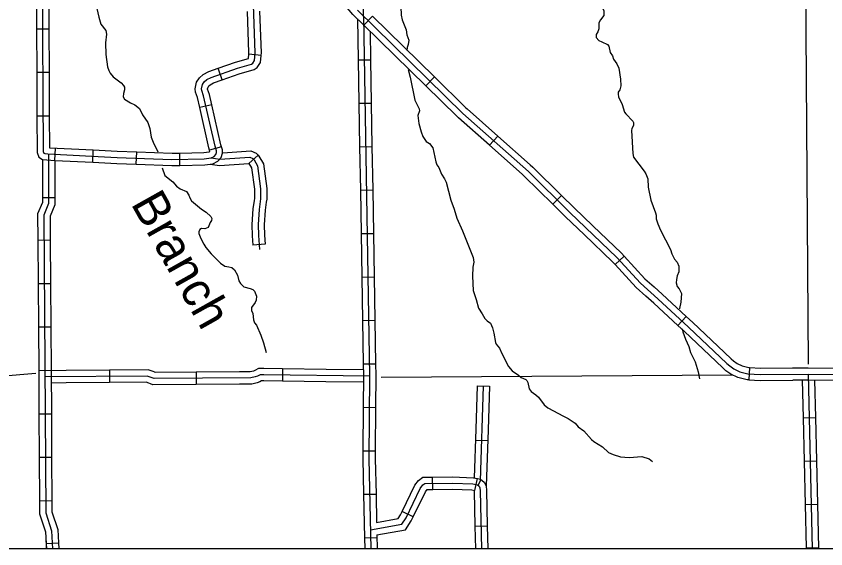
# Model space of a CAD drawing. Extents: x 1212896 to 1368412, y 378476 to 478763.
# Drawn here: x 1279495 to 1289328, y 388319 to 394792 of the extents above; entities that cross this region are included whole.
import ezdxf

# ---------------------------------------------------------------- set-up
doc = ezdxf.new("R2010")
doc.units = 0
for name, color, linetype in [('1', 7, 'Continuous'), ('Level 31', 7, 'Continuous'), ('Level 32', 7, 'Continuous'), ('Level 35', 7, 'Continuous'), ('Level 4', 7, 'Continuous'), ('Level 45', 7, 'Continuous'), ('Level 5', 7, 'Continuous')]:
    doc.layers.add(name, color=color, linetype=linetype)

msp = doc.modelspace()

# ---------------------------------------------------------------- linework, layer by layer
at = {"layer": '1'}
msp.add_lwpolyline([(1257400.3, 437504), (1319317.3, 437504), (1319317.3, 388319.3), (1257400.3, 388319.3)], close=True, dxfattribs=at)
at = {"layer": 'Level 31'}
for p, q in [((1283820.7, 394792.1), (1283715.7, 394684.9)), ((1284470, 393945.9), (1284575, 394053)), ((1285343.5, 393334.8), (1285244, 393222.6)), ((1285244, 393222.6), (1285244, 393222.6)), ((1285244, 393222.6), (1285244, 393222.6)), ((1286013.4, 392505.6), (1286118.8, 392612.4)), ((1286013.4, 392505.6), (1286013.4, 392505.6)), ((1286880, 391875.1), (1286769.4, 391773.8)), ((1287530.4, 391034.4), (1287632.3, 391144.5)), ((1287632.3, 391144.5), (1287632.3, 391144.5)), ((1287530.4, 391034.4), (1287530.4, 391034.4)), ((1288400.4, 390521.3), (1288393.8, 390371.5)), ((1288393.8, 390371.5), (1288393.8, 390371.5))]:
    msp.add_line(p, q, dxfattribs=at)
for points in [[(1283715.7, 394684.9), (1283584.6, 394813.4), (1283358, 395082)], [(1283638.6, 394863.5), (1284918.5, 393609.4), (1285715.4, 392903.1), (1286218.3, 392406.9), (1286791.1, 391859.1), (1287077.4, 391546.6), (1287288.1, 391358.8), (1287661.9, 391013.1), (1288126.6, 390571.2), (1288160.2, 390541.9), (1288211.1, 390506.9), (1288284.5, 390471.4), (1288382.2, 390445.7), (1288533.2, 390439), (1289114, 390442.4), (1294519.9, 390389.6)], [(1283820.7, 394792.1), (1284197.8, 394422.5)], [(1283715.7, 394684.9), (1284092.9, 394315.4)], [(1284197.8, 394422.5), (1284575, 394053)], [(1284470, 393945.9), (1284092.9, 394315.4)], [(1284575, 394053), (1284952.1, 393683.5)], [(1284847.1, 393576.3), (1284470, 393945.9)], [(1284952.1, 393683.5), (1284970.6, 393665.3), (1285343.5, 393334.8)], [(1285244, 393222.6), (1284868.3, 393555.6), (1284847.1, 393576.3)], [(1285343.5, 393334.8), (1285738.6, 392984.6)], [(1285244, 393222.6), (1285639.1, 392872.4)], [(1285738.6, 392984.6), (1285767.6, 392959), (1286118.8, 392612.4)], [(1286013.4, 392505.6), (1285665.1, 392849.4), (1285639.1, 392872.4)], [(1286118.8, 392612.4), (1286271.5, 392461.7), (1286497.2, 392245.9)], [(1286393.5, 392137.5), (1286167, 392354.1), (1286013.4, 392505.6)], [(1286497.2, 392245.9), (1286845.7, 391912.6), (1286880, 391875.1)], [(1286769.4, 391773.8), (1286738.5, 391807.6), (1286393.5, 392137.5)], [(1286880, 391875.1), (1287131.1, 391601.1), (1287242, 391502.2)], [(1286769.4, 391773.8), (1287025.6, 391494.2), (1287142.2, 391390.2)], [(1287242, 391502.2), (1287339.4, 391415.3), (1287632.3, 391144.5)], [(1287530.4, 391034.4), (1287238.6, 391304.3), (1287142.2, 391390.2)], [(1287632.3, 391144.5), (1287714.1, 391068.8), (1288016.7, 390781.1)], [(1287913.4, 390672.4), (1287611.5, 390959.4), (1287530.4, 391034.4)], [(1288016.7, 390781.1), (1288178.1, 390627.7), (1288207.1, 390602.3), (1288249.5, 390573.2), (1288311.1, 390543.4), (1288393.7, 390521.6), (1288400.4, 390521.3)], [(1288393.8, 390371.5), (1288371, 390372.5), (1288258.8, 390402), (1288174, 390443.1), (1288115, 390483.6), (1288077, 390516.8), (1287913.4, 390672.4)], [(1288400.4, 390521.3), (1288534.6, 390515.4), (1288924.4, 390517.7)], [(1288924.4, 390517.7), (1289114.1, 390518.8), (1289453.6, 390515.5)], [(1288393.8, 390371.5), (1288531.8, 390365.3), (1288925.3, 390367.7)], [(1289452.2, 390365.5), (1289113.9, 390368.8), (1288925.3, 390367.7)]]:
    msp.add_lwpolyline(points, dxfattribs=at)
at = {"layer": 'Level 32'}
for p, q in [((1279739.9, 394637.8), (1279889.9, 394638.8)), ((1282469.3, 394316), (1282320.1, 394331.7)), ((1283648.5, 394261.1), (1283798.4, 394263.6)), ((1279743.5, 394109.8), (1279893.4, 394110.9)), ((1281997.1, 394017.7), (1281947.5, 394159.3)), ((1281869.7, 393715.5), (1281723.4, 393682)), ((1283657.1, 393733.2), (1283807.1, 393735.6)), ((1279747, 393581.9), (1279897, 393582.9)), ((1279965.9, 393040), (1279973.4, 393189.8)), ((1280424, 393016.6), (1280431.5, 393166.4)), ((1280952.4, 392993.4), (1280958, 393143.3)), ((1281484.1, 392979.2), (1281481.6, 393129.1)), ((1281987.9, 393205.7), (1281844, 393163.2)), ((1283665.7, 393205.2), (1283815.7, 393207.7)), ((1279817.9, 393050.8), (1279963.6, 393039.6)), ((1283674.4, 392677.3), (1283824.4, 392679.8)), ((1279812.8, 392589.3), (1279962.8, 392588.6)), ((1283683, 392149.4), (1283833, 392151.8)), ((1279757.3, 392071.9), (1279907.3, 392072.9)), ((1283691.7, 391621.5), (1283841.7, 391623.9)), ((1279760.9, 391543.9), (1279910.9, 391544.9)), ((1283700.3, 391093.5), (1283850.3, 391096)), ((1279764.4, 391015.9), (1279914.4, 391016.9)), ((1283709, 390565.6), (1283858.9, 390568.1)), ((1279768, 390487.9), (1279918, 390488.9)), ((1283709.1, 390039.3), (1283859.1, 390038.4)), ((1279771.5, 389959.9), (1279921.5, 389960.9)), ((1289052.2, 389912.9), (1289202.1, 389916.2)), ((1283706.1, 389511.3), (1283856.1, 389510.4)), ((1279775.1, 389431.9), (1279925.1, 389432.9)), ((1289064, 389385), (1289213.9, 389388.4)), ((1284554.2, 389041.1), (1284552.7, 389191.1)), ((1285065.9, 389027), (1285095.6, 389174)), ((1279778.6, 388903.9), (1279928.6, 388904.9)), ((1283714.7, 388981.4), (1283864.7, 388984.6)), ((1289075.7, 388857.2), (1289225.7, 388860.5)), ((1284316.1, 388707), (1284180.9, 388772.1)), ((1285065.3, 388594.7), (1285215.3, 388598.3)), ((1283726, 388453.5), (1283876, 388456.7)), ((1279858.5, 388384.9), (1280008.4, 388391.6)), ((1289087.5, 388329.3), (1289237.5, 388332.6))]:
    msp.add_line(p, q, dxfattribs=at)
for points in [[(1279809.4, 395251.7), (1279823.5, 393145.8), (1279829.4, 393128.3), (1279840.9, 393121.6), (1279878.9, 393117.4), (1280719, 393075.7), (1281386.2, 393051.1), (1281779.2, 393057.7), (1281860.8, 393069.5), (1281898.3, 393088.4), (1281919.7, 393111.9), (1281927.2, 393135.1), (1281925.8, 393156.2), (1281909.6, 393210.9), (1281769.6, 393822.7), (1281748.2, 393889), (1281744.6, 393909.4), (1281755.5, 393960.5), (1281777.4, 393993.4), (1281808, 394020.6), (1281863.3, 394048.9), (1282181.9, 394160.5), (1282353.4, 394209.8), (1282368.4, 394220.3), (1282388.7, 394252.8), (1282398.6, 394347.3), (1282330.7, 396220.3)], [(1279736.4, 395165.8), (1279739.9, 394637.8)], [(1279886.4, 395166.8), (1279889.9, 394638.8)], [(1282320.1, 394331.7), (1282322.1, 394349.9), (1282304, 394848.5)], [(1282469.3, 394316), (1282472.3, 394344.7), (1282453.9, 394853.9)], [(1283713.4, 394790.2), (1283784.9, 390427.2), (1283779.1, 389413.7), (1283802.5, 388319.3)], [(1283640.3, 394758.8), (1283648.5, 394261.1)], [(1279739.9, 394637.8), (1279743.5, 394109.8)], [(1279889.9, 394638.8), (1279893.4, 394110.9)], [(1283792.8, 394609.4), (1283798.4, 394263.6)], [(1281947.5, 394159.3), (1282158.7, 394233.3), (1282314.4, 394278.1), (1282314.5, 394278.3), (1282320.1, 394331.7)], [(1281997.1, 394017.7), (1282204.3, 394090.3), (1282385.5, 394142.4), (1282423, 394168.6), (1282460.1, 394228.3), (1282469.3, 394316)], [(1283648.5, 394261.1), (1283657.1, 393733.2)], [(1283798.4, 394263.6), (1283807.1, 393735.6)], [(1279743.5, 394109.8), (1279747, 393581.9)], [(1279893.4, 394110.9), (1279897, 393582.9)], [(1281723.4, 393682), (1281695.9, 393802.4), (1281673.9, 393870.4), (1281666.7, 393910.7), (1281683.9, 393990.8), (1281719.3, 394043.9), (1281764.5, 394084.2), (1281833.1, 394119.3), (1281947.5, 394159.3)], [(1281869.7, 393715.5), (1281840.7, 393842.2), (1281819.8, 393906.9), (1281819.6, 393908.1), (1281824.6, 393931.4), (1281833.5, 393944.7), (1281849.9, 393959.4), (1281892.3, 393981.1), (1281997.1, 394017.7)], [(1281987.9, 393205.7), (1281980.8, 393229.6), (1281869.7, 393715.5)], [(1283657.1, 393733.2), (1283665.7, 393205.2)], [(1283807.1, 393735.6), (1283815.7, 393207.7)], [(1281844, 393163.2), (1281835.7, 393191.6), (1281723.4, 393682)], [(1279747, 393581.9), (1279750, 393133.6), (1279768.3, 393078.7), (1279814.8, 393051.6)], [(1279897, 393582.9), (1279899.6, 393192.9), (1279904.1, 393192.7)], [(1279904.1, 393192.7), (1280431.5, 393166.4)], [(1280431.5, 393166.4), (1280722.3, 393152), (1280958, 393143.3)], [(1280958, 393143.3), (1281387, 393127.6), (1281481.6, 393129.1)], [(1281481.6, 393129.1), (1281773.1, 393134), (1281837.6, 393143.3), (1281848.3, 393148.7), (1281844, 393163.2)], [(1281484.1, 392979.2), (1281785.1, 392984.2), (1281883.2, 392998.4), (1281943.5, 393028.7), (1281984.9, 393074.1), (1282001.6, 393126.1), (1281998.6, 393169.3), (1281987.9, 393205.7)], [(1283665.7, 393205.2), (1283674.4, 392677.3)], [(1283815.7, 393207.7), (1283824.4, 392679.8)], [(1279814.8, 393051.6), (1279812.8, 392589.3)], [(1279888.7, 393117), (1279886.1, 392514.2), (1279828.9, 392375.9), (1279853.2, 388757.5), (1279925.3, 388539.4), (1279935.2, 388319.3)], [(1279964.8, 393039.5), (1279962.8, 392588.6)], [(1279964.8, 393039.5), (1280424, 393016.6)], [(1280424, 393016.6), (1280715.9, 393002.1), (1280952.4, 392993.4)], [(1280952.4, 392993.4), (1281385.5, 392977.5), (1281484.1, 392979.2)], [(1283674.4, 392677.3), (1283683, 392149.4)], [(1283824.4, 392679.8), (1283833, 392151.8)], [(1279812.8, 392589.3), (1279812.6, 392529), (1279755.2, 392390.3), (1279757.3, 392071.9)], [(1279962.8, 392588.6), (1279962.4, 392498.8), (1279905.4, 392360.9), (1279907.3, 392072.9)], [(1283683, 392149.4), (1283691.7, 391621.5)], [(1283833, 392151.8), (1283841.7, 391623.9)], [(1279757.3, 392071.9), (1279760.9, 391543.9)], [(1279907.3, 392072.9), (1279910.9, 391544.9)], [(1283691.7, 391621.5), (1283700.3, 391093.5)], [(1283841.7, 391623.9), (1283850.3, 391096)], [(1279760.9, 391543.9), (1279764.4, 391015.9)], [(1279910.9, 391544.9), (1279914.4, 391016.9)], [(1283700.3, 391093.5), (1283709, 390565.6)], [(1283850.3, 391096), (1283858.9, 390568.1)], [(1279764.4, 391015.9), (1279768, 390487.9)], [(1279914.4, 391016.9), (1279918, 390488.9)], [(1283709, 390565.6), (1283711.2, 390426.8), (1283709.1, 390039.3)], [(1283858.9, 390568.1), (1283861.2, 390427.6), (1283859.1, 390038.4)], [(1279768, 390487.9), (1279771.5, 389959.9)], [(1279918, 390488.9), (1279921.5, 389960.9)], [(1289042, 390368.4), (1289052.2, 389912.9)], [(1289114, 390442.4), (1289161.4, 388319.3)], [(1289192.1, 390368), (1289202.1, 389916.2)], [(1283709.1, 390039.3), (1283706.1, 389511.3)], [(1283859.1, 390038.4), (1283856.1, 389510.4)], [(1279771.5, 389959.9), (1279775.1, 389431.9)], [(1279921.5, 389960.9), (1279925.1, 389432.9)], [(1289052.2, 389912.9), (1289064, 389385)], [(1289202.1, 389916.2), (1289213.9, 389388.4)], [(1283706.1, 389511.3), (1283705.5, 389413.1), (1283714.7, 388981.4)], [(1283856.1, 389510.4), (1283855.5, 389414.3), (1283864.7, 388984.6)], [(1279775.1, 389431.9), (1279778.6, 388903.9)], [(1279925.1, 389432.9), (1279928.6, 388904.9)], [(1289064, 389385), (1289075.7, 388857.2)], [(1289213.9, 389388.4), (1289225.7, 388860.5)], [(1284180.9, 388772.1), (1284335.4, 389092.7), (1284379.5, 389150), (1284432.3, 389189.9), (1284552.7, 389191.1)], [(1284552.7, 389191.1), (1284794.7, 389193.5), (1285048.4, 389183.5), (1285095.6, 389174)], [(1283798.1, 388549.4), (1284179.8, 388617.6), (1284229, 388695.8), (1284400.8, 389052.4), (1284433.8, 389095.2), (1284458.3, 389113.8), (1284793.5, 389117.1), (1285039.2, 389107.5), (1285097.4, 389095.7), (1285116.7, 389079.1), (1285126.1, 389062.3), (1285128.7, 389023.4), (1285145.5, 388319.3)], [(1285095.6, 389174), (1285132.1, 389166.6), (1285176.9, 389128.1), (1285201.1, 389084.5), (1285205.1, 389026.9), (1285215.3, 388598.3)], [(1284316.1, 388707), (1284463.8, 389013.6), (1284484.5, 389040.5), (1284554.2, 389041.1)], [(1284554.2, 389041.1), (1284792.5, 389043.5), (1285030.4, 389034.1), (1285065.9, 389027)], [(1285054.5, 389029.3), (1285055.2, 389020), (1285065.3, 388594.7)], [(1279778.6, 388903.9), (1279779.7, 388745.4), (1279852.2, 388525.9), (1279858.5, 388384.9)], [(1279928.6, 388904.9), (1279929.5, 388770.1), (1280001.1, 388553.3), (1280008.4, 388391.6)], [(1283714.7, 388981.4), (1283726, 388453.5)], [(1283864.7, 388984.6), (1283872.1, 388640.2)], [(1289075.7, 388857.2), (1289087.5, 388329.3)], [(1289225.7, 388860.5), (1289237.5, 388332.6)], [(1283872.1, 388640.2), (1284133.1, 388686.8), (1284162, 388732.9), (1284180.9, 388772.1)], [(1283875.3, 388488.4), (1284224.8, 388550.8), (1284293.5, 388660.2), (1284316.1, 388707)], [(1285215.3, 388598.3), (1285221.9, 388319.3)], [(1285065.3, 388594.7), (1285071.9, 388319.3)], [(1283726, 388453.5), (1283728.9, 388319.3)], [(1283875.3, 388488.4), (1283878.9, 388319.3)], [(1279858.5, 388384.9), (1279861.5, 388319.3)], [(1280008.4, 388391.6), (1280011.5, 388322.5), (1280011.8, 388319.3)], [(1289087.5, 388329.3), (1289087.7, 388319.3)], [(1289237.5, 388332.6), (1289237.8, 388319.3)]]:
    msp.add_lwpolyline(points, dxfattribs=at)
at = {"layer": 'Level 35'}
for points in [[(1286192.5, 395676.1), (1286268, 395460.2), (1286351.9, 395278.6), (1286382.9, 395227.2), (1286471.2, 395159.9), (1286481.5, 395144.1), (1286490.5, 395054.1), (1286538.9, 394997.6), (1286567.3, 394939.2), (1286584.1, 394915.5), (1286616.2, 394890.8), (1286630.4, 394861.7), (1286630.8, 394798.6), (1286591, 394749.6), (1286571.2, 394710.1), (1286569.1, 394636.4), (1286559.3, 394603.5), (1286539, 394571), (1286538.8, 394533.9)], [(1284177.3, 395419.6), (1284191.1, 395383.8), (1284206.8, 395301.9), (1284188.8, 395214.3), (1284155.7, 395177.5), (1284137.4, 395100.4), (1284139.6, 395044.9), (1284160, 394981.1), (1284162.8, 394942.1), (1284158.4, 394915), (1284169.9, 394845), (1284170.8, 394804), (1284181.6, 394748.9), (1284229.6, 394625.8), (1284238.1, 394563.4), (1284264.3, 394502.3), (1284256.5, 394446), (1284243.3, 394412.6), (1284240.5, 394375.4)], [(1280473.8, 394883.6), (1280497, 394780.8), (1280522.9, 394694.2), (1280583.4, 394617.3), (1280591.4, 394573.4), (1280580.7, 394469.9), (1280584.8, 394327.7)], [(1286538.8, 394533.9), (1286569.6, 394495.5), (1286608.8, 394482.3), (1286676.4, 394448.7), (1286690.9, 394427), (1286709.5, 394352.2), (1286735.3, 394310.7), (1286750.2, 394269.9), (1286791.4, 394211.7), (1286812.5, 394160), (1286833.4, 394025.2), (1286838.2, 393945.1), (1286826.2, 393897.7), (1286806.9, 393870.2), (1286804.4, 393846.1), (1286811.1, 393813.2), (1286855.1, 393718.9), (1286884.4, 393625.1), (1286897.5, 393605.6), (1286983.2, 393518.2), (1286991.7, 393498.4), (1286992.4, 393463.3), (1286972.3, 393425.8), (1286969.1, 393401), (1286982.9, 393122.3), (1286992.9, 393079.4), (1287121.3, 392909.8), (1287140, 392878.1), (1287165.3, 392815.3), (1287171.5, 392715.4), (1287200.9, 392556.7), (1287260, 392402.7), (1287266.8, 392372.7), (1287268.8, 392327.6), (1287289.1, 392266.9), (1287320.7, 392191.5), (1287440.6, 391956.5), (1287456.3, 391903.3), (1287491.1, 391838.3), (1287522.8, 391803.9), (1287541.8, 391754.2), (1287543.4, 391685.1), (1287522.4, 391638.5), (1287512.4, 391593.2), (1287511.3, 391552.1), (1287523.3, 391507.3), (1287544.9, 391479.7), (1287574.1, 391421.2), (1287567.4, 391316.8), (1287551, 391240.3), (1287551, 391236.3)], [(1280584.8, 394327.7), (1280605.4, 394176.5), (1280621.1, 394130), (1280636.7, 394100.3), (1280671.6, 394056.9), (1280771, 393980.9), (1280799.7, 393948.5), (1280808.1, 393928.6), (1280808.8, 393895.6), (1280796.8, 393853.2), (1280794.7, 393813), (1280810.3, 393783.3), (1280884.1, 393737.8), (1280935.5, 393715.9), (1280991.4, 393670), (1281029, 393594.6), (1281093.6, 393500.8), (1281117.5, 393427.2), (1281135.8, 393320.3), (1281164.5, 393241.8), (1281207.1, 393164.5), (1281213, 393141.6)], [(1284253.9, 394144.7), (1284280.1, 394052.6), (1284335.2, 393773.1), (1284389.4, 393668), (1284391.9, 393643), (1284371.3, 393583.5), (1284386.4, 393486.6), (1284411.5, 393387.9), (1284431.7, 393330.2), (1284474.1, 393269.2), (1284515.6, 393246), (1284556.5, 393190.6), (1284590.2, 393020.9), (1284602.9, 392985.1), (1284629.6, 392953.6), (1284661.4, 392874), (1284697.1, 392816.1), (1284715.4, 392773), (1284774, 392556.8), (1284814.3, 392446.4), (1284845.6, 392338.9), (1284916.9, 392182), (1285043.7, 391860), (1285053, 391801.1), (1285040.3, 391742.7), (1285035.8, 391632.3), (1285045.6, 391458.1), (1285080.9, 391350.7)], [(1281268.7, 392950), (1281301.7, 392855.8), (1281398.2, 392778.8), (1281442.2, 392727.6), (1281487.9, 392692.5), (1281562.4, 392663.1), (1281591.3, 392616.6), (1281603, 392584.8), (1281624.8, 392546.2), (1281743.7, 392447.5), (1281801.9, 392408.7), (1281859.8, 392358.2), (1281871.9, 392332.9), (1281867.5, 392307.9), (1281848.8, 392286.6), (1281824.6, 392222.9), (1281786.9, 392207.9), (1281746.9, 392210), (1281725.1, 392201.4), (1281714.8, 392172.2), (1281714.3, 392149.2), (1281737.6, 392090.5), (1281772, 392021.9), (1281798.9, 391980.6), (1281861.4, 391904.8), (1281974.7, 391791), (1282027.4, 391754.1), (1282078.4, 391747), (1282113.6, 391736.9), (1282146, 391711.5), (1282182.4, 391645.2), (1282197, 391577.3), (1282220.6, 391541.8), (1282260.4, 391502.5)], [(1282260.4, 391502.5), (1282337.6, 391484.2), (1282366.9, 391470.8), (1282387.3, 391449.2), (1282411.6, 391387.6), (1282409.6, 391342.4), (1282396.3, 391314.1), (1282351.8, 391249.9), (1282353.5, 391215.9), (1282370.4, 391180.3), (1282375.1, 391100.3), (1282390.7, 391067.4), (1282413.3, 391037.8), (1282464.8, 390917.6), (1282499.9, 390821.2), (1282531.1, 390705.8)], [(1285080.9, 391350.7), (1285109.2, 391242), (1285154.6, 391174.8), (1285184.7, 391118.4), (1285216.3, 391089), (1285255.8, 391061.8), (1285278, 391005.1), (1285295.4, 390940.4), (1285315.9, 390824.5), (1285325.3, 390805.7), (1285366.3, 390759.5), (1285394.7, 390690.9), (1285474.9, 390536.3), (1285517, 390483.1), (1285597, 390428.7), (1285626.6, 390399.3), (1285684, 390375.5), (1285697.2, 390365.8), (1285709.8, 390339), (1285726.4, 390263.2), (1285747.1, 390229.5), (1285805.8, 390191.7), (1285838.4, 390161.4), (1285908.3, 390069.7), (1285952, 390034.5), (1286139.9, 389930.4), (1286197.3, 389904.6), (1286283.5, 389844.3), (1286320.3, 389803), (1286389.2, 389754.4), (1286482.3, 389649.2), (1286511.9, 389621.8), (1286617, 389559.9), (1286688.4, 389491.3), (1286746.9, 389463.5), (1286832.3, 389436.3), (1286938.2, 389427.6), (1287091.6, 389441), (1287184.1, 389412.9), (1287223.7, 389378.7)], [(1287584.7, 390990.7), (1287591.6, 390956.4), (1287624.2, 390865.9), (1287665, 390778.6), (1287684.6, 390706.9), (1287742, 390589.9), (1287778.6, 390469.4), (1287792.4, 390384.5)]]:
    msp.add_lwpolyline(points, dxfattribs=at)
at = {"layer": 'Level 4'}
msp.add_lwpolyline([(1279855.7, 388472.7), (1279857, 388319.3)], dxfattribs=at)
at = {"layer": 'Level 45'}
for p, q in [((1282433.2, 393101.7), (1282322, 393001)), ((1282518.8, 392020.2), (1282369.2, 392008.2)), ((1280628.6, 390489.4), (1280629.8, 390339.4)), ((1281679.7, 390466.6), (1281680.5, 390316.6)), ((1282729.8, 390506.2), (1282728, 390356.2)), ((1285094.3, 390299.5), (1285244.2, 390294.5)), ((1285074.6, 389640.5), (1285224.6, 389635.4))]:
    msp.add_line(p, q, dxfattribs=at)
for points in [[(1283713.4, 394790.2), (1283698.2, 395698.8), (1283748.5, 395760), (1287570.2, 395763), (1287617.1, 395785.1), (1287641.4, 395805), (1287660, 395831.4), (1287674.1, 395871.8), (1287675, 395921.9), (1287631.3, 397955.8), (1287632.7, 397985.9), (1287657.7, 398074.7), (1287701.3, 398178.9), (1287722.9, 398287.6), (1287728.7, 398386.9), (1287725.5, 398941.2), (1287745, 399007.8), (1287773.5, 399043.9), (1287793.9, 399047.7), (1287914.7, 399005.5), (1288007.6, 398953.4), (1288121.3, 398821.5)], [(1282003.2, 393131), (1282344.4, 393153.9), (1282411.1, 393126), (1282433.2, 393101.7)], [(1281860.8, 393069.5), (1281967.9, 393054.8), (1282332, 393079.3), (1282367.6, 393064.4), (1282383, 393047.4), (1282426.5, 392974.2), (1282463.8, 392694.8), (1282463.5, 392572.5), (1282445.4, 392441.8), (1282434.4, 392259.1), (1282436.3, 392126.9), (1282450, 391956.7)], [(1282433.2, 393101.7), (1282442.5, 393091.4), (1282497.5, 392998.8), (1282537.4, 392699.6), (1282537.1, 392567.3), (1282532, 392530.6)], [(1281851.2, 392993.8), (1281965.2, 392978.1), (1282319.2, 393001.8), (1282322.4, 393000.5)], [(1282321.2, 393001.8), (1282352.8, 392948.6), (1282387.4, 392689.8), (1282387.1, 392577.9), (1282383.4, 392551.1)], [(1282383.4, 392551.1), (1282369.3, 392449.3), (1282358, 392260.9), (1282360, 392123.2), (1282369.2, 392008.2)], [(1282532, 392530.6), (1282518.7, 392434.5), (1282508.1, 392257.4), (1282509.9, 392130.3), (1282518.8, 392020.2)], [(1280100.6, 390484.9), (1279918, 390483.4)], [(1280628.6, 390489.4), (1280100.6, 390484.9)], [(1281179.6, 390464.9), (1281157.2, 390473.3), (1281096.9, 390493.4), (1280628.6, 390489.4)], [(1281679.7, 390466.6), (1281182.1, 390463.9), (1281179.6, 390464.9)], [(1282207.7, 390469.4), (1281679.7, 390466.6)], [(1282729.8, 390506.2), (1282503.7, 390509), (1282438.5, 390509), (1282394, 390486.7), (1282375.8, 390479.4), (1282337.1, 390470.1), (1282207.7, 390469.4)], [(1283257.8, 390499.7), (1282729.8, 390506.2)], [(1283710.1, 390494.2), (1283257.8, 390499.7)], [(1283784.8, 390418.3), (1282503.3, 390434), (1282456.2, 390434), (1282424.8, 390418.3), (1282398.6, 390407.8), (1282346.2, 390395.2), (1281168.7, 390388.8), (1281132.1, 390402.6), (1281085, 390418.3), (1279842.1, 390407.7)], [(1280101.9, 390334.9), (1279919, 390333.4)], [(1280629.8, 390339.4), (1280101.9, 390334.9)], [(1281126.9, 390324.4), (1281107.1, 390331.9), (1281073.1, 390343.2), (1280629.8, 390339.4)], [(1281680.5, 390316.6), (1281155.3, 390313.8), (1281126.9, 390324.4)], [(1282208.5, 390319.4), (1281680.5, 390316.6)], [(1282728, 390356.2), (1282502.8, 390359), (1282473.9, 390359), (1282455.5, 390349.8), (1282421.5, 390336.2), (1282355.4, 390320.2), (1282208.5, 390319.4)], [(1283255.9, 390349.8), (1282728, 390356.2)], [(1283710.8, 390344.2), (1283255.9, 390349.8)], [(1285094.3, 390299.5), (1285076.6, 389771.8)], [(1285167.8, 390297.1), (1285129.2, 389144.5), (1285105.5, 389090.9)], [(1285244.2, 390294.5), (1285226.5, 389766.8)], [(1285076.6, 389771.8), (1285056.9, 389183.2)], [(1285226.5, 389766.8), (1285203.5, 389080.1)]]:
    msp.add_lwpolyline(points, dxfattribs=at)
at = {"layer": 'Level 5'}
for points in [[(1289076.7, 395763.7), (1289113.2, 390562.5)], [(1274535.2, 390017), (1279734.9, 390453)], [(1283927.3, 390403.9), (1288196.2, 390435.6)]]:
    msp.add_lwpolyline(points, dxfattribs=at)

# ---------------------------------------------------------------- texts
at = {"layer": 'Level 35'}
msp.add_text('Branch', height=422.4, rotation=299.32612, dxfattribs=at).set_placement((1280881.1, 392516.1))

doc.saveas('drawing.dxf')
